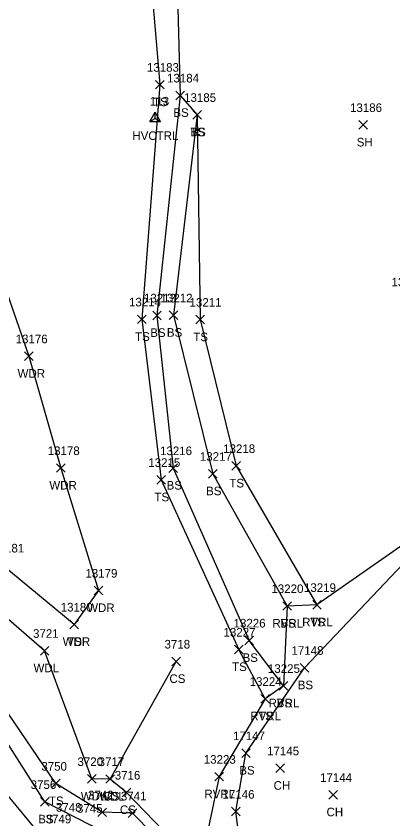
# Model space of a CAD drawing. Extents: x 1482574 to 1485769, y 580696 to 595649.
# Drawn here: x 1483911.4 to 1483999, y 583242.6 to 583429.1 of the extents above; entities that cross this region are included whole.
import ezdxf

# ---------------------------------------------------------------- set-up
doc = ezdxf.new("R2010")
doc.units = 0
for name, color, linetype in [('C_A', 7, 'Continuous'), ('C_I', 7, 'Continuous'), ('CPSM', 7, 'Continuous'), ('D_I', 7, 'Continuous'), ('L_A', 7, 'Continuous'), ('L_I', 7, 'Continuous'), ('L_TIC', 7, 'Continuous'), ('LAWA', 7, 'Continuous'), ('LAWE', 7, 'Continuous'), ('LELB', 7, 'Continuous')]:
    doc.layers.add(name, color=color, linetype=linetype)

msp = doc.modelspace()

# ---------------------------------------------------------------- linework, layer by layer
at = {"layer": 'CPSM'}
for p, q in [((1483942.48, 583404.56), (1483943.73, 583406.73)), ((1483942.48, 583404.56), (1483943.73, 583405.28)), ((1483944.98, 583404.56), (1483943.73, 583406.73)), ((1483943.73, 583405.28), (1483943.73, 583406.73)), ((1483943.73, 583405.28), (1483943.73, 583405.28)), ((1483943.73, 583405.28), (1483944.98, 583404.56)), ((1483942.48, 583404.56), (1483944.98, 583404.56))]:
    msp.add_line(p, q, dxfattribs=at)
at = {"layer": 'L_TIC'}
for points in [[(1483943.83, 583412.13), (1483945.83, 583414.13)], [(1483945.83, 583412.13), (1483943.83, 583414.13)], [(1483948.51, 583409.64), (1483950.51, 583411.64)], [(1483950.51, 583409.64), (1483948.51, 583411.64)], [(1483948.51, 583409.64), (1483950.51, 583411.64)], [(1483950.51, 583409.64), (1483948.51, 583411.64)], [(1483952.47, 583405.13), (1483954.47, 583407.13)], [(1483954.47, 583405.13), (1483952.47, 583407.13)], [(1483952.47, 583405.13), (1483954.47, 583407.13)], [(1483954.47, 583405.13), (1483952.47, 583407.13)], [(1483991.08, 583402.78), (1483993.08, 583404.78)], [(1483993.08, 583402.78), (1483991.08, 583404.78)], [(1483943.14, 583358.56), (1483945.14, 583360.56)], [(1483945.14, 583358.56), (1483943.14, 583360.56)], [(1483947, 583358.59), (1483949, 583360.59)], [(1483949, 583358.59), (1483947, 583360.59)], [(1483939.65, 583357.64), (1483941.65, 583359.64)], [(1483941.65, 583357.64), (1483939.65, 583359.64)], [(1483953.17, 583357.57), (1483955.17, 583359.57)], [(1483955.17, 583357.57), (1483953.17, 583359.57)], [(1483913.38, 583349.08), (1483915.38, 583351.08)], [(1483915.38, 583349.08), (1483913.38, 583351.08)], [(1483920.77, 583323.12), (1483922.77, 583325.12)], [(1483922.77, 583323.12), (1483920.77, 583325.12)], [(1483946.93, 583323.11), (1483948.93, 583325.11)], [(1483948.93, 583323.11), (1483946.93, 583325.11)], [(1483961.55, 583323.6), (1483963.55, 583325.6)], [(1483963.55, 583323.6), (1483961.55, 583325.6)], [(1483956.12, 583321.79), (1483958.12, 583323.79)], [(1483958.12, 583321.79), (1483956.12, 583323.79)], [(1483944.14, 583320.38), (1483946.14, 583322.38)], [(1483946.14, 583320.38), (1483944.14, 583322.38)], [(1483929.55, 583294.67), (1483931.55, 583296.67)], [(1483931.55, 583294.67), (1483929.55, 583296.67)], [(1483973.4, 583291.08), (1483975.4, 583293.08)], [(1483975.4, 583291.08), (1483973.4, 583293.08)], [(1483973.4, 583291.08), (1483975.4, 583293.08)], [(1483975.4, 583291.08), (1483973.4, 583293.08)], [(1483980.32, 583291.35), (1483982.32, 583293.35)], [(1483982.32, 583291.35), (1483980.32, 583293.35)], [(1483980.32, 583291.35), (1483982.32, 583293.35)], [(1483982.32, 583291.35), (1483980.32, 583293.35)], [(1483923.87, 583286.8), (1483925.87, 583288.8)], [(1483925.87, 583286.8), (1483923.87, 583288.8)], [(1483923.87, 583286.8), (1483925.87, 583288.8)], [(1483925.87, 583286.8), (1483923.87, 583288.8)], [(1483964.59, 583283.09), (1483966.59, 583285.09)], [(1483966.59, 583283.09), (1483964.59, 583285.09)], [(1483964.59, 583283.09), (1483966.59, 583285.09)], [(1483966.59, 583283.09), (1483964.59, 583285.09)], [(1483917.04, 583280.69), (1483919.04, 583282.69)], [(1483919.04, 583280.69), (1483917.04, 583282.69)], [(1483962.19, 583280.99), (1483964.19, 583282.99)], [(1483964.19, 583280.99), (1483962.19, 583282.99)], [(1483962.19, 583280.99), (1483964.19, 583282.99)], [(1483964.19, 583280.99), (1483962.19, 583282.99)], [(1483947.59, 583278.21), (1483949.59, 583280.21)], [(1483949.59, 583278.21), (1483947.59, 583280.21)], [(1483977.41, 583276.75), (1483979.41, 583278.75)], [(1483979.41, 583276.75), (1483977.41, 583278.75)], [(1483972.51, 583272.55), (1483974.51, 583274.55)], [(1483974.51, 583272.55), (1483972.51, 583274.55)], [(1483972.51, 583272.55), (1483974.51, 583274.55)], [(1483974.51, 583272.55), (1483972.51, 583274.55)], [(1483968.26, 583269.54), (1483970.26, 583271.54)], [(1483970.26, 583269.54), (1483968.26, 583271.54)], [(1483968.26, 583269.54), (1483970.26, 583271.54)], [(1483970.26, 583269.54), (1483968.26, 583271.54)], [(1483963.82, 583256.93), (1483965.82, 583258.93)], [(1483965.82, 583256.93), (1483963.82, 583258.93)], [(1483971.76, 583253.42), (1483973.76, 583255.42)], [(1483973.76, 583253.42), (1483971.76, 583255.42)], [(1483928.01, 583250.93), (1483930.01, 583252.93)], [(1483930.01, 583250.93), (1483928.01, 583252.93)], [(1483932.27, 583250.91), (1483934.27, 583252.91)], [(1483934.27, 583250.91), (1483932.27, 583252.91)], [(1483932.27, 583250.91), (1483934.27, 583252.91)], [(1483934.27, 583250.91), (1483932.27, 583252.91)], [(1483957.6, 583251.46), (1483959.6, 583253.46)], [(1483959.6, 583251.46), (1483957.6, 583253.46)], [(1483919.62, 583249.85), (1483921.62, 583251.85)], [(1483921.62, 583249.85), (1483919.62, 583251.85)], [(1483936.08, 583247.78), (1483938.08, 583249.78)], [(1483938.08, 583247.78), (1483936.08, 583249.78)], [(1483984.05, 583247.25), (1483986.05, 583249.25)], [(1483986.05, 583247.25), (1483984.05, 583249.25)], [(1483917.11, 583245.6), (1483919.11, 583247.6)], [(1483919.11, 583245.6), (1483917.11, 583247.6)], [(1483930.38, 583243.18), (1483932.38, 583245.17)], [(1483932.38, 583243.18), (1483930.38, 583245.17)], [(1483937.44, 583242.96), (1483939.44, 583244.95)], [(1483939.44, 583242.96), (1483937.44, 583244.95)], [(1483961.44, 583243.35), (1483963.44, 583245.35)], [(1483963.44, 583243.35), (1483961.44, 583245.35)]]:
    msp.add_lwpolyline(points, dxfattribs=at)
at = {"layer": 'LAWA'}
for points in [[(1483803.2, 583735.12), (1483825.14, 583713.33), (1483843.38, 583669.74), (1483862.33, 583628.74), (1483871.69, 583603.07), (1483882.64, 583564.44), (1483894.89, 583516.14), (1483900.52, 583463.64), (1483903.73, 583428.05), (1483902.34, 583384.57), (1483914.38, 583350.08), (1483921.77, 583324.12), (1483930.55, 583295.67), (1483924.87, 583287.8)], [(1484017, 583127.07), (1483992.32, 583151.64), (1483986.75, 583162.55), (1483967.23, 583184.52), (1483961.14, 583191.5), (1483958.58, 583194.81), (1483938.8, 583221.92), (1483921.75, 583233.27), (1483898.52, 583261.31), (1483880.67, 583282.01), (1483878.22, 583292.39), (1483867.31, 583307.12), (1483858.51, 583327.08), (1483839.59, 583353.88), (1483824.82, 583372.64), (1483793.64, 583424.35), (1483780.64, 583444.54)], [(1483933.27, 583251.91), (1483929.01, 583251.93), (1483918.04, 583281.69), (1483898.84, 583298.22), (1483895.73, 583312.03), (1483888.12, 583332.41)]]:
    msp.add_lwpolyline(points, dxfattribs=at)
at = {"layer": 'LAWE'}
for points in [[(1484096.51, 583594.8), (1484124.11, 583550.5), (1484141.62, 583514.22), (1484141.7, 583495.5), (1484137.47, 583476.54), (1484124.63, 583457.15), (1484113.5, 583428.7), (1484104.65, 583402.59), (1484092.97, 583397.84), (1484086.3, 583397.24), (1484074.61, 583392.28), (1484060.51, 583358.08), (1484034.64, 583320.09), (1484005.63, 583309.27), (1483981.32, 583292.35), (1483974.4, 583292.08), (1483973.51, 583273.55)], [(1483973.51, 583273.55), (1483969.26, 583270.54)], [(1483969.26, 583270.54), (1483958.6, 583252.46)], [(1483958.6, 583252.46), (1483954.08, 583231.16)]]:
    msp.add_lwpolyline(points, dxfattribs=at)
at = {"layer": 'LELB'}
for points in [[(1483764.89, 583869.31), (1483766.47, 583848.33), (1483773.02, 583835.43), (1483788.15, 583817.33), (1483797.07, 583803.46), (1483802.69, 583789.66), (1483809.82, 583753.25), (1483830.69, 583716.93), (1483860.8, 583678.02), (1483884.63, 583637.37), (1483911.6, 583615.28), (1483935.25, 583580.48), (1483920.79, 583529.49), (1483935.8, 583480.6), (1483941.99, 583445.87), (1483944.83, 583413.13), (1483940.65, 583358.64), (1483945.14, 583321.38), (1483963.19, 583281.99)], [(1483806.98, 583791.11), (1483811.44, 583753.6), (1483836.28, 583720.23), (1483869.17, 583683.74), (1483895.56, 583644.56), (1483921.85, 583621.21), (1483948.02, 583584.38), (1483941.41, 583532.53), (1483943.93, 583484.29), (1483948.63, 583445.45), (1483949.51, 583410.64), (1483944.14, 583359.56), (1483947.93, 583324.11), (1483965.59, 583284.09)], [(1483949.51, 583410.64), (1483953.47, 583406.13), (1483948, 583359.59), (1483957.12, 583322.79), (1483974.4, 583292.08), (1483973.51, 583273.55), (1483965.59, 583284.09)], [(1483953.47, 583406.13), (1483954.17, 583358.57), (1483962.55, 583324.6), (1483981.32, 583292.35)], [(1484134.32, 583041.83), (1484124.78, 583054.91), (1484117.02, 583058.63), (1484101.02, 583072.3), (1484085.52, 583086.06), (1484074.21, 583096.81), (1484059.27, 583112.71), (1484034.01, 583132.93), (1484019.38, 583154.26), (1484003.66, 583168.66), (1483989.55, 583189.28), (1483976.67, 583206.55), (1483964.81, 583226.25), (1483962.44, 583244.35), (1483964.82, 583257.93), (1483978.41, 583277.75), (1484007.1, 583307.94), (1484038.55, 583320.82), (1484060.82, 583355.47), (1484075.41, 583386.22)], [(1484017.45, 583150.68), (1484002.85, 583166.73), (1483991.78, 583181.88), (1483982.29, 583191.11), (1483960.91, 583220.19), (1483947.81, 583234.43), (1483938.44, 583243.95), (1483931.38, 583244.18), (1483920.62, 583250.85), (1483908.15, 583269.18), (1483901.72, 583283.67), (1483890.61, 583303.06), (1483888.74, 583306.39), (1483879.88, 583327.09)], [(1483924.87, 583287.8), (1483908.31, 583301.51), (1483901.04, 583319.94)], [(1484014.11, 583148.62), (1483997.68, 583164.14), (1483990.38, 583180.75), (1483982.52, 583187.36), (1483957.2, 583217.61), (1483944.82, 583230.69), (1483928.81, 583241.08), (1483918.11, 583246.6), (1483906.81, 583264.23), (1483889.36, 583284.48), (1483880.94, 583299), (1483874.12, 583317.92)], [(1483969.26, 583270.54), (1483963.19, 583281.99)], [(1483954.08, 583231.16), (1483937.08, 583248.78), (1483933.27, 583251.91), (1483948.59, 583279.21)]]:
    msp.add_lwpolyline(points, dxfattribs=at)

# ---------------------------------------------------------------- texts
at = {"layer": 'C_A'}
msp.add_text('HVCTRL', height=2, dxfattribs=at).set_placement((1483938.42, 583400.28))
at = {"layer": 'C_I'}
msp.add_text('113', height=2, dxfattribs=at).set_placement((1483942.5, 583408.28))
at = {"layer": 'D_I'}
msp.add_text('3749', height=2, dxfattribs=at).set_placement((1483918.27, 583241.63))
at = {"layer": 'L_A'}
for s, p in [('TS', (1483943.24, 583408.13)), ('BS', (1483947.95, 583405.64)), ('BS', (1483947.95, 583405.64)), ('TS', (1483951.87, 583401.13)), ('BS', (1483951.91, 583401.13)), ('SH', (1483990.56, 583398.78)), ('BS', (1483942.58, 583354.56)), ('BS', (1483946.44, 583354.59)), ('TS', (1483939.06, 583353.64)), ('TS', (1483952.58, 583353.57)), ('WDR', (1483911.75, 583345.08)), ('WDR', (1483919.13, 583319.12)), ('BS', (1483946.37, 583319.11)), ('TS', (1483960.96, 583319.6)), ('BS', (1483955.56, 583317.79)), ('TS', (1483943.55, 583316.38)), ('WDR', (1483927.91, 583290.67)), ('RVRL', (1483977.88, 583287.35)), ('TS', (1483979.73, 583287.35)), ('RVRL', (1483970.97, 583287.08)), ('BS', (1483972.85, 583287.08)), ('WDR', (1483922.23, 583282.8)), ('TS', (1483923.28, 583282.8)), ('BS', (1483964.03, 583279.09)), ('BS', (1483964.03, 583279.09)), ('WDL', (1483915.45, 583276.69)), ('TS', (1483961.6, 583276.99)), ('TS', (1483961.6, 583276.99)), ('CS', (1483947.03, 583274.21)), ('BS', (1483976.85, 583272.75)), ('RVRL', (1483970.08, 583268.55)), ('BS', (1483971.96, 583268.55)), ('RVRL', (1483965.82, 583265.54)), ('TS', (1483967.67, 583265.54)), ('BS', (1483963.26, 583252.93)), ('CH', (1483971.24, 583249.42)), ('WDL', (1483926.43, 583246.93)), ('WDL', (1483930.69, 583246.91)), ('CS', (1483931.71, 583246.91)), ('RVRL', (1483955.17, 583247.46)), ('TS', (1483919.03, 583245.85)), ('CS', (1483935.52, 583243.78)), ('CH', (1483983.54, 583243.25)), ('BS', (1483916.55, 583241.6))]:
    msp.add_text(s, height=2, dxfattribs=at).set_placement(p)
at = {"layer": 'L_I'}
for s, p in [('13183', (1483941.81, 583416.13)), ('13184', (1483946.48, 583413.64)), ('13184', (1483946.48, 583413.64)), ('13185', (1483950.44, 583409.13)), ('13185', (1483950.44, 583409.13)), ('13186', (1483989, 583406.78)), ('13210', (1483998.64, 583366.29)), ('13213', (1483941.12, 583362.56)), ('13212', (1483944.97, 583362.59)), ('13214', (1483937.63, 583361.64)), ('13211', (1483951.71, 583361.57)), ('13176', (1483911.3, 583353.08)), ('13178', (1483918.75, 583327.12)), ('13216', (1483944.85, 583327.11)), ('13218', (1483959.52, 583327.6)), ('13217', (1483954.1, 583325.79)), ('13215', (1483942.12, 583324.38)), ('13181', (1483905.85, 583304.51)), ('13179', (1483927.51, 583298.67)), ('13220', (1483970.73, 583295.08)), ('13220', (1483970.73, 583295.08)), ('13219', (1483978.29, 583295.35)), ('13219', (1483978.29, 583295.35)), ('13180', (1483921.76, 583290.8)), ('13180', (1483921.76, 583290.8)), ('13226', (1483961.94, 583287.09)), ('13226', (1483961.94, 583287.09)), ('3721', (1483915.34, 583284.69)), ('13227', (1483959.6, 583284.99)), ('13227', (1483959.6, 583284.99)), ('3718', (1483945.89, 583282.21)), ('17148', (1483975.39, 583280.75)), ('13225', (1483969.92, 583276.55)), ('13225', (1483969.92, 583276.55)), ('13224', (1483965.67, 583273.54)), ('13224', (1483965.67, 583273.54)), ('17147', (1483961.8, 583260.93)), ('17145', (1483969.73, 583257.42)), ('3750', (1483917.27, 583253.85)), ('3720', (1483925.67, 583254.93)), ('3717', (1483930.58, 583254.91)), ('3717', (1483930.58, 583254.91)), ('13223', (1483955.01, 583255.46)), ('3716', (1483934.33, 583251.78)), ('17144', (1483982.03, 583251.25)), ('3756', (1483914.79, 583249.6)), ('3742', (1483928.12, 583247.18)), ('3741', (1483935.75, 583246.95)), ('17146', (1483959.37, 583247.35)), ('3748', (1483920.66, 583244.32)), ('3745', (1483925.55, 583244.08))]:
    msp.add_text(s, height=2, dxfattribs=at).set_placement(p)

doc.saveas('drawing.dxf')
